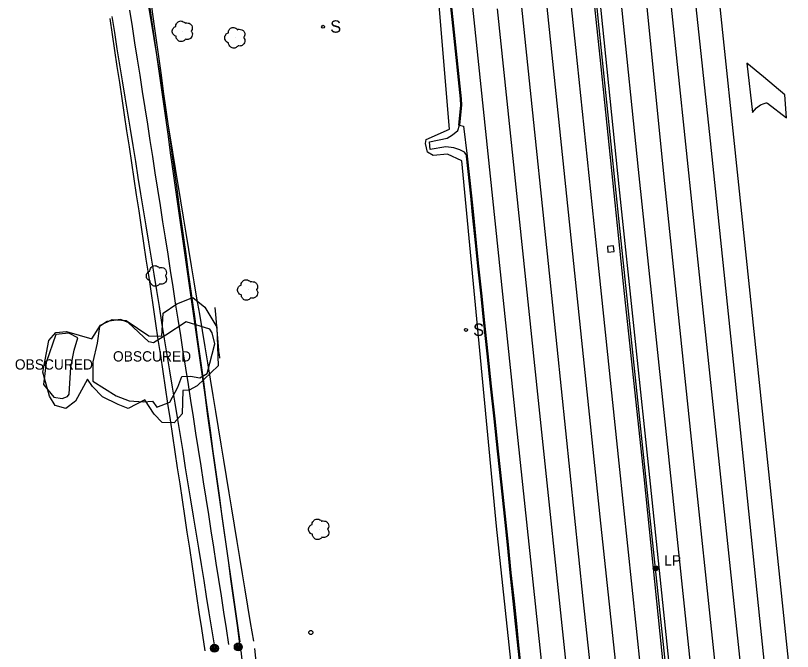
# Model space of a CAD drawing. Extents: x 368532 to 392481, y 10654822 to 10676899.
# Drawn here: x 375343 to 375720, y 10669688.9 to 10669997.6 of the extents above; entities that cross this region are included whole.
import ezdxf

# ---------------------------------------------------------------- set-up
doc = ezdxf.new("R2010")
doc.units = 0
for name, color, linetype in [('p_Catenary', 7, 'Continuous'), ('p_drainage conc drain', 7, 'Continuous'), ('p_drainage culvert', 7, 'Continuous'), ('p_dtm obscured area', 7, 'Continuous'), ('p_road - paved curb', 7, 'Continuous'), ('p_road guard rails', 7, 'Continuous'), ('p_road paint stripe', 7, 'Continuous'), ('p_structure constr area', 7, 'Continuous'), ('p_structure sign', 7, 'Continuous'), ('p_structure unidentified', 7, 'Continuous'), ('p_utility general pole', 7, 'Continuous'), ('p_utility guy anchor', 7, 'Continuous'), ('p_veg tree', 7, 'Continuous'), ('p_veg woods', 7, 'Continuous')]:
    doc.layers.add(name, color=color, linetype=linetype)

msp = doc.modelspace()

# ---------------------------------------------------------------- linework, layer by layer
at = {"layer": 'p_Catenary'}
for points in [[(375407.44, 10670002.09), (375408.75, 10669994.21), (375410.05, 10669986.34), (375411.35, 10669978.47), (375412.65, 10669970.6), (375413.95, 10669962.73), (375415.25, 10669954.86), (375416.55, 10669946.99), (375417.85, 10669939.12), (375419.15, 10669931.25), (375420.45, 10669923.38), (375421.75, 10669915.51), (375423.05, 10669907.63), (375424.35, 10669899.76), (375425.65, 10669891.89), (375426.95, 10669884.02), (375428.25, 10669876.15), (375429.55, 10669868.28), (375430.85, 10669860.41), (375432.15, 10669852.54), (375433.45, 10669844.67), (375434.75, 10669836.8), (375436.05, 10669828.92), (375437.35, 10669821.05), (375438.65, 10669813.18), (375439.95, 10669805.31), (375441.25, 10669797.44), (375442.55, 10669789.57), (375443.85, 10669781.7), (375445.15, 10669773.83), (375446.45, 10669765.96), (375447.75, 10669758.09), (375449.05, 10669750.21), (375450.35, 10669742.34), (375451.65, 10669734.47), (375452.96, 10669726.6), (375454.26, 10669718.73), (375455.56, 10669710.86), (375456.86, 10669702.99), (375458.36, 10669693.88)], [(375451.89, 10669693.53), (375450.77, 10669701.45), (375449.65, 10669709.37), (375448.52, 10669717.28), (375447.4, 10669725.2), (375446.28, 10669733.11), (375445.16, 10669741.03), (375444.04, 10669748.94), (375442.91, 10669756.86), (375441.79, 10669764.77), (375440.67, 10669772.69), (375439.55, 10669780.6), (375438.43, 10669788.52), (375437.3, 10669796.43), (375436.18, 10669804.35), (375435.06, 10669812.26), (375433.94, 10669820.18), (375432.81, 10669828.1), (375431.69, 10669836.01), (375430.57, 10669843.93), (375429.45, 10669851.84), (375428.33, 10669859.76), (375427.2, 10669867.67), (375426.08, 10669875.59), (375424.96, 10669883.5), (375423.84, 10669891.42), (375422.72, 10669899.33), (375421.59, 10669907.25), (375420.47, 10669915.16), (375419.35, 10669923.08), (375418.23, 10669930.99), (375417.11, 10669938.91), (375415.98, 10669946.83), (375414.86, 10669954.74), (375413.74, 10669962.66), (375412.62, 10669970.57), (375411.5, 10669978.49), (375410.37, 10669986.4), (375409.25, 10669994.32), (375408.13, 10670002.23)], [(375408.97, 10670001.84), (375410.28, 10669992.34), (375411.37, 10669984.45), (375412.46, 10669976.55), (375413.55, 10669968.66), (375414.64, 10669960.77), (375415.73, 10669952.88), (375416.82, 10669944.99), (375417.91, 10669937.09), (375419, 10669929.2), (375420.09, 10669921.31), (375421.18, 10669913.42), (375422.27, 10669905.53), (375423.36, 10669897.63), (375424.45, 10669889.74), (375425.54, 10669881.85), (375426.63, 10669873.96), (375427.72, 10669866.07), (375428.81, 10669858.17), (375429.9, 10669850.28), (375430.99, 10669842.39), (375432.08, 10669834.5), (375433.16, 10669826.6), (375434.25, 10669818.71), (375435.34, 10669810.82), (375436.43, 10669802.93), (375437.52, 10669795.04), (375438.61, 10669787.14), (375439.7, 10669779.25), (375440.79, 10669771.36), (375441.88, 10669763.47), (375442.97, 10669755.58), (375444.06, 10669747.68), (375445.15, 10669739.79), (375446.24, 10669731.9), (375447.33, 10669724.01), (375448.42, 10669716.12), (375449.51, 10669708.22), (375450.6, 10669700.33), (375451.69, 10669692.44)], [(375389.63, 10669997.11), (375390.91, 10669989.29), (375392.18, 10669981.47), (375393.46, 10669973.64), (375394.73, 10669965.82), (375396.01, 10669958), (375397.28, 10669950.18), (375398.56, 10669942.36), (375399.83, 10669934.53), (375401.11, 10669926.71), (375402.38, 10669918.89), (375403.66, 10669911.07), (375404.93, 10669903.25), (375406.21, 10669895.42), (375407.48, 10669887.6), (375408.76, 10669879.78), (375410.03, 10669871.96), (375411.31, 10669864.14), (375412.58, 10669856.31), (375413.86, 10669848.49), (375415.13, 10669840.67), (375416.41, 10669832.85), (375417.68, 10669825.03), (375418.96, 10669817.2), (375420.23, 10669809.38), (375421.51, 10669801.56), (375422.78, 10669793.74), (375424.06, 10669785.92), (375425.33, 10669778.09), (375426.61, 10669770.27), (375427.88, 10669762.45), (375429.16, 10669754.63), (375430.43, 10669746.81), (375431.71, 10669738.98), (375432.98, 10669731.16), (375434.26, 10669723.34), (375435.53, 10669715.52), (375436.81, 10669707.7), (375438.08, 10669699.88), (375439.36, 10669692.05)], [(375446.54, 10669692.21), (375445.31, 10669700.11), (375444.08, 10669708), (375442.84, 10669715.9), (375441.61, 10669723.8), (375440.38, 10669731.69), (375439.14, 10669739.59), (375437.91, 10669747.48), (375436.68, 10669755.38), (375435.45, 10669763.27), (375434.21, 10669771.17), (375432.98, 10669779.07), (375431.75, 10669786.96), (375430.51, 10669794.86), (375429.28, 10669802.75), (375428.05, 10669810.65), (375426.81, 10669818.54), (375425.58, 10669826.44), (375424.35, 10669834.34), (375423.11, 10669842.23), (375421.88, 10669850.13), (375420.65, 10669858.02), (375419.41, 10669865.92), (375418.18, 10669873.81), (375416.95, 10669881.71), (375415.71, 10669889.61), (375414.48, 10669897.5), (375413.25, 10669905.4), (375412.01, 10669913.29), (375410.78, 10669921.19), (375409.55, 10669929.08), (375408.31, 10669936.98), (375407.08, 10669944.88), (375405.85, 10669952.77), (375404.61, 10669960.67), (375403.38, 10669968.56), (375402.15, 10669976.46), (375400.91, 10669984.35), (375399.68, 10669992.25), (375398.45, 10670000.15)], [(375434.94, 10669689.28), (375433.31, 10669700.11), (375432.14, 10669707.9), (375430.97, 10669715.7), (375429.8, 10669723.49), (375428.63, 10669731.28), (375427.46, 10669739.07), (375426.29, 10669746.86), (375425.12, 10669754.65), (375423.95, 10669762.45), (375422.78, 10669770.24), (375421.61, 10669778.03), (375420.44, 10669785.82), (375419.26, 10669793.61), (375418.09, 10669801.4), (375416.92, 10669809.2), (375415.75, 10669816.99), (375414.58, 10669824.78), (375413.41, 10669832.57), (375412.24, 10669840.36), (375411.07, 10669848.16), (375409.9, 10669855.95), (375408.73, 10669863.74), (375407.56, 10669871.53), (375406.39, 10669879.32), (375405.22, 10669887.11), (375404.05, 10669894.91), (375402.88, 10669902.7), (375401.71, 10669910.49), (375400.54, 10669918.28), (375399.37, 10669926.07), (375398.19, 10669933.87), (375397.02, 10669941.66), (375395.85, 10669949.45), (375394.68, 10669957.24), (375393.51, 10669965.03), (375392.34, 10669972.82), (375391.17, 10669980.62), (375390, 10669988.41), (375388.83, 10669996.2)], [(375453.56, 10669679.12), (375452.51, 10669689.25)], [(375458.9, 10669690.38), (375460, 10669679.37)]]:
    msp.add_lwpolyline(points, dxfattribs=at)
at = {"layer": 'p_drainage conc drain'}
for p, q in [((375705.93, 10669967.88), (375697.86, 10669974.46)), ((375716.28, 10669959.14), (375705.93, 10669967.88)), ((375717.09, 10669947.88), (375716.28, 10669959.14)), ((375700.66, 10669950.43), (375702.53, 10669952.7)), ((375702.53, 10669952.7), (375703.87, 10669953.77)), ((375703.87, 10669953.77), (375704.49, 10669954.22)), ((375704.49, 10669954.22), (375706.25, 10669954.9)), ((375706.25, 10669954.9), (375707.14, 10669955.19)), ((375707.14, 10669955.19), (375707.46, 10669955.19)), ((375707.46, 10669955.19), (375707.8, 10669955.08)), ((375707.8, 10669955.08), (375717.09, 10669947.88)), ((375557.54, 10669941.74), (375558.36, 10669944.28)), ((375554.96, 10669939.59), (375557.54, 10669941.74)), ((375543.85, 10669936.31), (375552.38, 10669938.07)), ((375552.38, 10669938.07), (375554.96, 10669939.59)), ((375544.24, 10669932.54), (375543.85, 10669936.31)), ((375551.75, 10669933.84), (375544.24, 10669932.54)), ((375555.64, 10669933.3), (375551.75, 10669933.84)), ((375558.52, 10669932.34), (375555.64, 10669933.3)), ((375560.83, 10669931.18), (375558.52, 10669932.34)), ((375562.16, 10669929.34), (375560.83, 10669931.18))]:
    msp.add_line(p, q, dxfattribs=at)
at = {"layer": 'p_drainage culvert'}
for p, q in [((375440.12, 10669852.47), (375439.84, 10669855.92)), ((375441.74, 10669833.19), (375440.12, 10669852.47)), ((375441.74, 10669833.19), (375441.9, 10669831.2))]:
    msp.add_line(p, q, dxfattribs=at)
at = {"layer": 'p_dtm obscured area'}
for points in [[(375380.52, 10669820.08), (375391.79, 10669812.99), (375398.06, 10669810.52), (375405.05, 10669810.04), (375409.37, 10669810.32), (375411.6, 10669807.48), (375417.79, 10669809.85), (375421.74, 10669817.14), (375423.59, 10669822.38), (375427.92, 10669822.57), (375432.45, 10669821.66), (375435.88, 10669823.84), (375439.71, 10669838.26), (375438.39, 10669843.61), (375437.25, 10669845.34), (375425.7, 10669848.97), (375415.81, 10669842.4), (375409.85, 10669838.66), (375407.61, 10669839.25), (375397.6, 10669848.63), (375393.91, 10669850.01), (375387.48, 10669848.99), (375383.76, 10669846.59), (375382.58, 10669838.48), (375380.48, 10669829.51)], [(375368.92, 10669813.86), (375369.75, 10669826.83), (375371.35, 10669835.18), (375373.18, 10669841.14), (375368.86, 10669843.47), (375362.48, 10669842.78), (375357.83, 10669829.19), (375356.52, 10669818.4), (375361.58, 10669812.27), (375365.57, 10669811.69), (375368.23, 10669812.64)]]:
    msp.add_lwpolyline(points, close=True, dxfattribs=at)
at = {"layer": 'p_road - paved curb'}
for p, q in [((375626.65, 10669977.33), (375621.51, 10670025)), ((375624.48, 10670025.31), (375635.75, 10669914.51)), ((375552.93, 10670012.66), (375555.32, 10669989.5)), ((375553.28, 10670012.69), (375555.67, 10669989.53)), ((375553.43, 10670012.71), (375555.82, 10669989.55)), ((375555.32, 10669989.5), (375558.71, 10669957.13)), ((375555.67, 10669989.53), (375559.06, 10669957.16)), ((375555.82, 10669989.55), (375559.21, 10669957.17)), ((375638.55, 10669862.61), (375626.65, 10669977.33)), ((375697.86, 10669974.46), (375700.66, 10669950.43)), ((375558.71, 10669957.13), (375558.85, 10669954.08)), ((375559.06, 10669957.16), (375559.2, 10669954.07)), ((375559.21, 10669957.17), (375559.35, 10669954.07)), ((375558.85, 10669954.08), (375557.87, 10669944.33)), ((375559.2, 10669954.07), (375558.21, 10669944.3)), ((375559.35, 10669954.07), (375558.36, 10669944.28)), ((375558.36, 10669944.28), (375560.26, 10669943.91)), ((375560.26, 10669943.91), (375562.16, 10669929.34)), ((375561.67, 10669929.28), (375563.67, 10669909.93)), ((375562.01, 10669929.32), (375564.02, 10669909.96)), ((375562.16, 10669929.34), (375564.17, 10669909.98)), ((375635.75, 10669914.51), (375650.93, 10669770.31)), ((375563.67, 10669909.93), (375564.62, 10669900.77)), ((375564.02, 10669909.96), (375564.97, 10669900.8)), ((375564.17, 10669909.98), (375565.12, 10669900.82)), ((375564.62, 10669900.77), (375566.01, 10669887.16)), ((375564.97, 10669900.8), (375566.36, 10669887.19)), ((375565.12, 10669900.82), (375566.51, 10669887.21)), ((375566.01, 10669887.16), (375567.18, 10669875.93)), ((375566.36, 10669887.19), (375567.53, 10669875.96)), ((375566.51, 10669887.21), (375567.68, 10669875.98)), ((375567.18, 10669875.93), (375568.7, 10669861.34)), ((375567.53, 10669875.96), (375569.05, 10669861.37)), ((375567.68, 10669875.98), (375569.2, 10669861.39)), ((375568.7, 10669861.34), (375569.92, 10669849.74)), ((375569.05, 10669861.37), (375570.27, 10669849.77)), ((375569.2, 10669861.39), (375570.42, 10669849.79)), ((375647.99, 10669773.73), (375638.55, 10669862.61)), ((375569.92, 10669849.74), (375571.65, 10669833.36)), ((375570.27, 10669849.77), (375572, 10669833.39)), ((375570.42, 10669849.79), (375572.15, 10669833.41)), ((375571.65, 10669833.36), (375573.33, 10669817.69)), ((375572, 10669833.39), (375573.68, 10669817.72)), ((375572.15, 10669833.41), (375573.83, 10669817.74)), ((375573.33, 10669817.69), (375574.99, 10669801.75)), ((375573.68, 10669817.72), (375575.34, 10669801.78)), ((375573.83, 10669817.74), (375575.49, 10669801.8)), ((375574.99, 10669801.75), (375576.65, 10669786.11)), ((375575.34, 10669801.78), (375577, 10669786.14)), ((375575.49, 10669801.8), (375577.15, 10669786.16)), ((375576.65, 10669786.11), (375578.38, 10669769.78)), ((375577, 10669786.14), (375578.73, 10669769.81)), ((375577.15, 10669786.16), (375578.88, 10669769.83)), ((375658.4, 10669672.52), (375647.99, 10669773.73)), ((375578.38, 10669769.78), (375580.02, 10669754.5)), ((375578.73, 10669769.81), (375580.37, 10669754.53)), ((375578.88, 10669769.83), (375580.52, 10669754.55)), ((375650.93, 10669770.31), (375662.75, 10669655.85)), ((375580.02, 10669754.5), (375581.45, 10669740.73)), ((375580.37, 10669754.53), (375581.8, 10669740.76)), ((375580.52, 10669754.55), (375581.95, 10669740.78)), ((375581.45, 10669740.73), (375582.87, 10669727.06)), ((375581.8, 10669740.76), (375583.22, 10669727.09)), ((375581.95, 10669740.78), (375583.37, 10669727.11)), ((375582.87, 10669727.06), (375584.36, 10669713.32)), ((375583.22, 10669727.09), (375584.71, 10669713.35)), ((375583.37, 10669727.11), (375584.86, 10669713.37)), ((375584.36, 10669713.32), (375585.48, 10669702.36)), ((375584.71, 10669713.35), (375585.83, 10669702.39)), ((375584.86, 10669713.37), (375585.98, 10669702.41)), ((375585.48, 10669702.36), (375586.43, 10669693.45)), ((375585.83, 10669702.39), (375586.78, 10669693.48)), ((375585.98, 10669702.41), (375586.93, 10669693.5)), ((375586.43, 10669693.45), (375587.7, 10669681.32)), ((375586.78, 10669693.48), (375588.05, 10669681.35)), ((375586.93, 10669693.5), (375588.2, 10669681.37))]:
    msp.add_line(p, q, dxfattribs=at)
at = {"layer": 'p_road guard rails'}
for p, q in [((375625.69, 10669996.24), (375623.04, 10670022.8)), ((375636.27, 10669894.38), (375625.69, 10669996.24)), ((375649.63, 10669766.11), (375636.27, 10669894.38)), ((375659.64, 10669671.41), (375649.63, 10669766.11))]:
    msp.add_line(p, q, dxfattribs=at)
at = {"layer": 'p_road paint stripe'}
for p, q in [((375670.18, 10670028.73), (375680, 10669936.74)), ((375605.79, 10669954.99), (375598.74, 10670023.84)), ((375634.49, 10670025.94), (375645.16, 10669922.79)), ((375646.96, 10670025.36), (375657.95, 10669915.96)), ((375614.78, 10669982.03), (375610.53, 10670022.22)), ((375586.68, 10670018.78), (375605.61, 10669836.74)), ((375675.65, 10669863.9), (375659.82, 10670016.15)), ((375563.25, 10670014.88), (375573.3, 10669919.56)), ((375694.02, 10669915.32), (375684, 10670010.07)), ((375596.8, 10669810.76), (375576.82, 10670000.84)), ((375625.33, 10669881.06), (375614.78, 10669982.03)), ((375626.69, 10669754.29), (375605.79, 10669954.99)), ((375680, 10669936.74), (375691.94, 10669821.68)), ((375645.16, 10669922.79), (375659.08, 10669791.09)), ((375573.3, 10669919.56), (375585.51, 10669801.97)), ((375657.95, 10669915.96), (375670.76, 10669791.97)), ((375704.06, 10669819.42), (375694.02, 10669915.32)), ((375635.81, 10669780.31), (375625.33, 10669881.06)), ((375696.41, 10669667.18), (375675.65, 10669863.9)), ((375605.61, 10669836.74), (375618.32, 10669714.45)), ((375691.94, 10669821.68), (375703.91, 10669704.86)), ((375719.98, 10669666.86), (375704.06, 10669819.42)), ((375613.98, 10669646.73), (375596.8, 10669810.76)), ((375585.51, 10669801.97), (375601.72, 10669649.59)), ((375659.08, 10669791.09), (375671.67, 10669669.99)), ((375670.76, 10669791.97), (375687.06, 10669638.3)), ((375646.93, 10669674.93), (375635.81, 10669780.31)), ((375648.31, 10669549.6), (375626.69, 10669754.29)), ((375618.32, 10669714.45), (375635.9, 10669549.82)), ((375703.91, 10669704.86), (375719.57, 10669558.39))]:
    msp.add_line(p, q, dxfattribs=at)
at = {"layer": 'p_structure constr area'}
for p, q in [((375553.47, 10669942.37), (375547.11, 10670020.7)), ((375542.3, 10669937.46), (375553.47, 10669942.37)), ((375541.95, 10669935.45), (375542.3, 10669937.46)), ((375542.79, 10669931.29), (375541.95, 10669935.45)), ((375545.59, 10669929.71), (375542.79, 10669931.29)), ((375552.54, 10669930.31), (375545.59, 10669929.71)), ((375559.49, 10669927.07), (375552.54, 10669930.31)), ((375576.4, 10669749.69), (375559.49, 10669927.07)), ((375598.27, 10669545.28), (375576.4, 10669749.69))]:
    msp.add_line(p, q, dxfattribs=at)
at = {"layer": 'p_structure sign'}
for centre in [(375492.18, 10669992.14), (375561.54, 10669844.97)]:
    msp.add_circle(centre, 0.713, dxfattribs=at)
at = {"layer": 'p_structure unidentified'}
for p, q in [((375633.11, 10669885.86), (375630.14, 10669885.54)), ((375630.14, 10669885.54), (375630.44, 10669882.7)), ((375633.41, 10669883.02), (375633.11, 10669885.86)), ((375630.44, 10669882.7), (375633.41, 10669883.02))]:
    msp.add_line(p, q, dxfattribs=at)
at = {"layer": 'p_utility general pole'}
for centre, radius in [((375653.63, 10669729.28), 1.19), ((375653.63, 10669729.28), 0.901), ((375653.63, 10669729.28), 0.608), ((375653.63, 10669729.28), 0.337), ((375653.63, 10669729.28), 0.12), ((375439.48, 10669690.46), 1.9), ((375439.48, 10669690.46), 1.44), ((375451.04, 10669691.1), 1.9), ((375451.04, 10669691.1), 1.44), ((375451.04, 10669691.1), 0.973), ((375451.04, 10669691.1), 0.539), ((375439.48, 10669690.46), 0.973), ((375439.48, 10669690.46), 0.539), ((375439.48, 10669690.46), 0.192), ((375451.04, 10669691.1), 0.192)]:
    msp.add_circle(centre, radius, dxfattribs=at)
at = {"layer": 'p_utility guy anchor'}
msp.add_circle((375486.26, 10669698.09), 1, dxfattribs=at)
at = {"layer": 'p_veg tree'}
for p, q in [((375424.12, 10669989.99), (375424.12, 10669989.99)), ((375449.61, 10669986.85), (375449.61, 10669986.85)), ((375411.58, 10669871.24), (375411.58, 10669871.24)), ((375455.81, 10669864.42), (375455.81, 10669864.42)), ((375490.34, 10669748.26), (375490.34, 10669748.26))]:
    msp.add_line(p, q, dxfattribs=at)
for points in [[(375425.45, 10669986.04), (375424.24, 10669985.07), (375422.62, 10669985.01), (375421.41, 10669985.91), (375420.97, 10669986.63), (375420.85, 10669987.33), (375420.86, 10669987.48), (375420.76, 10669987.51), (375419.91, 10669987.96), (375418.98, 10669989.65), (375419.53, 10669991.48), (375420.6, 10669992.24), (375420.73, 10669992.29), (375420.73, 10669992.41), (375421.02, 10669993.59), (375422.2, 10669994.7), (375423.87, 10669994.81), (375424.82, 10669994.29), (375425.22, 10669993.9), (375425.27, 10669993.81), (375425.35, 10669993.88), (375426.01, 10669994.02), (375427.27, 10669993.79), (375428.43, 10669992.73), (375428.71, 10669991.37), (375428.36, 10669990.28), (375428.2, 10669990.07), (375428.19, 10669990), (375428.23, 10669989.95), (375428.47, 10669989.56), (375428.78, 10669988.64), (375428.54, 10669987.45), (375427.8, 10669986.44), (375426.28, 10669985.92), (375425.43, 10669986.03)], [(375450.94, 10669982.9), (375449.73, 10669981.93), (375448.11, 10669981.88), (375446.9, 10669982.77), (375446.46, 10669983.5), (375446.34, 10669984.19), (375446.35, 10669984.34), (375446.25, 10669984.37), (375445.4, 10669984.82), (375444.47, 10669986.52), (375445.02, 10669988.35), (375446.09, 10669989.1), (375446.22, 10669989.15), (375446.22, 10669989.27), (375446.51, 10669990.45), (375447.69, 10669991.57), (375449.36, 10669991.67), (375450.31, 10669991.15), (375450.71, 10669990.77), (375450.76, 10669990.67), (375450.84, 10669990.74), (375451.5, 10669990.88), (375452.76, 10669990.66), (375453.92, 10669989.59), (375454.2, 10669988.23), (375453.85, 10669987.15), (375453.69, 10669986.94), (375453.68, 10669986.87), (375453.72, 10669986.81), (375453.96, 10669986.43), (375454.27, 10669985.51), (375454.03, 10669984.32), (375453.28, 10669983.3), (375451.77, 10669982.78), (375450.92, 10669982.9)], [(375412.9, 10669867.3), (375411.69, 10669866.32), (375410.08, 10669866.27), (375408.87, 10669867.16), (375408.42, 10669867.89), (375408.3, 10669868.58), (375408.31, 10669868.73), (375408.21, 10669868.77), (375407.36, 10669869.22), (375406.43, 10669870.91), (375406.99, 10669872.74), (375408.05, 10669873.49), (375408.19, 10669873.55), (375408.18, 10669873.67), (375408.48, 10669874.85), (375409.65, 10669875.96), (375411.32, 10669876.06), (375412.28, 10669875.55), (375412.67, 10669875.16), (375412.72, 10669875.06), (375412.8, 10669875.13), (375413.46, 10669875.28), (375414.72, 10669875.05), (375415.88, 10669873.99), (375416.17, 10669872.62), (375415.82, 10669871.54), (375415.66, 10669871.33), (375415.65, 10669871.26), (375415.68, 10669871.21), (375415.92, 10669870.82), (375416.24, 10669869.9), (375415.99, 10669868.71), (375415.25, 10669867.69), (375413.73, 10669867.17), (375412.88, 10669867.29)], [(375457.14, 10669860.48), (375455.92, 10669859.5), (375454.31, 10669859.45), (375453.1, 10669860.34), (375452.66, 10669861.07), (375452.54, 10669861.76), (375452.55, 10669861.91), (375452.44, 10669861.95), (375451.6, 10669862.4), (375450.67, 10669864.09), (375451.22, 10669865.92), (375452.28, 10669866.67), (375452.42, 10669866.73), (375452.42, 10669866.85), (375452.71, 10669868.03), (375453.88, 10669869.14), (375455.55, 10669869.24), (375456.51, 10669868.73), (375456.9, 10669868.34), (375456.96, 10669868.24), (375457.04, 10669868.31), (375457.7, 10669868.46), (375458.96, 10669868.23), (375460.11, 10669867.17), (375460.4, 10669865.8), (375460.05, 10669864.72), (375459.89, 10669864.51), (375459.88, 10669864.44), (375459.91, 10669864.39), (375460.15, 10669864), (375460.47, 10669863.08), (375460.23, 10669861.89), (375459.48, 10669860.87), (375457.97, 10669860.35), (375457.12, 10669860.47)], [(375491.66, 10669744.31), (375490.45, 10669743.33), (375488.84, 10669743.28), (375487.63, 10669744.18), (375487.18, 10669744.9), (375487.06, 10669745.6), (375487.07, 10669745.75), (375486.97, 10669745.78), (375486.12, 10669746.23), (375485.19, 10669747.92), (375485.75, 10669749.75), (375486.81, 10669750.51), (375486.95, 10669750.56), (375486.94, 10669750.68), (375487.24, 10669751.86), (375488.41, 10669752.97), (375490.08, 10669753.08), (375491.04, 10669752.56), (375491.43, 10669752.17), (375491.48, 10669752.08), (375491.56, 10669752.14), (375492.22, 10669752.29), (375493.48, 10669752.06), (375494.64, 10669751), (375494.93, 10669749.64), (375494.57, 10669748.55), (375494.41, 10669748.34), (375494.41, 10669748.27), (375494.44, 10669748.22), (375494.68, 10669747.83), (375495, 10669746.91), (375494.75, 10669745.72), (375494.01, 10669744.7), (375492.49, 10669744.19), (375491.64, 10669744.3)]]:
    msp.add_spline(points, degree=3, dxfattribs=at)
at = {"layer": 'p_veg woods'}
msp.add_lwpolyline([(375424.1, 10669815.57), (375423.81, 10669804.29), (375419.86, 10669799.93), (375414.18, 10669800.1), (375410.29, 10669804.15), (375405.67, 10669811.02), (375397.53, 10669806.76), (375392.76, 10669808.72), (375385.23, 10669812.5), (375380.33, 10669817.44), (375377.85, 10669821.1), (375372.12, 10669810.43), (375367.39, 10669806.9), (375362.13, 10669808.21), (375359.47, 10669812.88), (375356.16, 10669824.52), (375359.14, 10669839.85), (375362.52, 10669843.77), (375367.75, 10669844.27), (375379.94, 10669840.63), (375384.2, 10669847.28), (375389.85, 10669849.99), (375396.66, 10669849.53), (375407.57, 10669842.04), (375413.89, 10669841.91), (375414.64, 10669853.12), (375421.22, 10669857.57), (375429.06, 10669860.76), (375434.79, 10669856.02), (375440.58, 10669846.24), (375441.3, 10669827.55), (375431.08, 10669817.79), (375427.23, 10669815.73)], close=True, dxfattribs=at)

# ---------------------------------------------------------------- texts
at = {"layer": 'p_dtm obscured area'}
for p in [(375388.39, 10669829.63), (375340.78, 10669825.71)]:
    msp.add_text(' OBSCURED', height=5, dxfattribs=at).set_placement(p)
at = {"layer": 'p_structure sign'}
for p in [(375495.64, 10669989.24), (375565, 10669842.07)]:
    msp.add_text('S', height=6, dxfattribs=at).set_placement(p)
at = {"layer": 'p_utility general pole'}
msp.add_text('LP', height=5, dxfattribs=at).set_placement((375657.74, 10669730.58))

doc.saveas('drawing.dxf')
